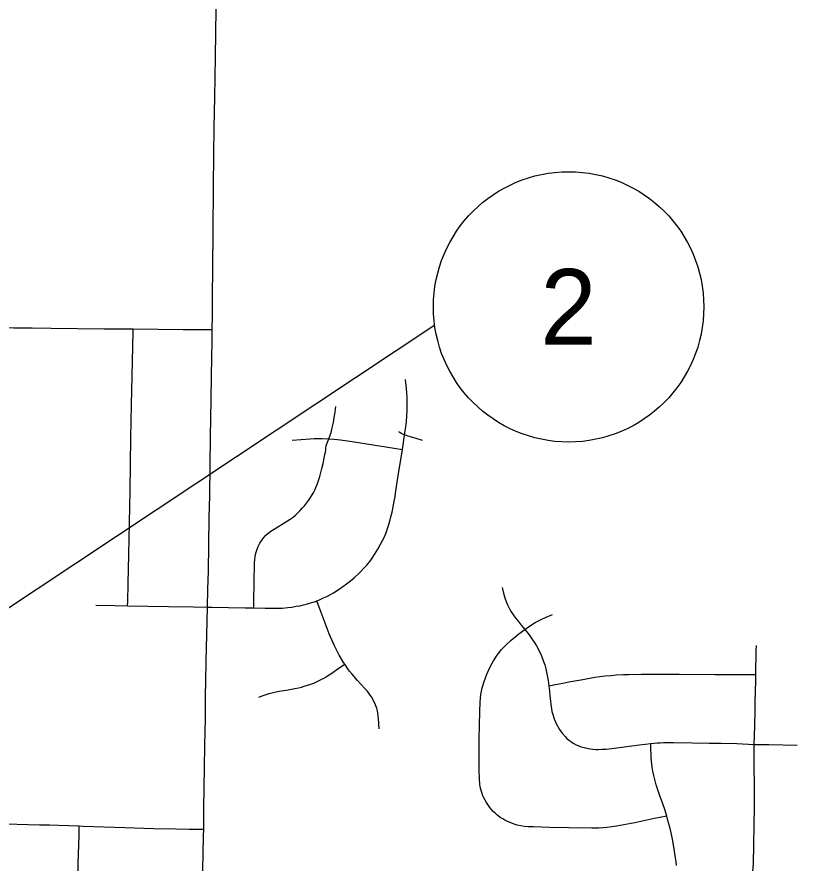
# Model space of a CAD drawing. Extents: x 1341221 to 1914484, y 79347 to 658398.
# Drawn here: x 1392720 to 1399302, y 615143 to 622283 of the extents above; entities that cross this region are included whole.
import ezdxf

# ---------------------------------------------------------------- set-up
doc = ezdxf.new("R2010")
doc.units = 0
for name, color, linetype in [('GM_X_County', 7, 'Continuous'), ('GM_X_State_Shield', 7, 'Continuous'), ('GM_X_US_Shield', 7, 'Continuous')]:
    doc.layers.add(name, color=color, linetype=linetype)

msp = doc.modelspace()

# ---------------------------------------------------------------- linework, layer by layer
at = {"layer": 'GM_X_County'}
msp.add_line((1396244.3, 619680.8), (1389506.6, 615209.7), dxfattribs=at)
msp.add_circle((1397374.4, 619836), 1140.7, dxfattribs=at)
at = {"layer": 'GM_X_State_Shield'}
for points in [[(1393653.5, 617314.5), (1393654.4, 617348.7), (1393658.6, 617500.9), (1393663.6, 617743.5), (1393673.9, 618283.1), (1393681.5, 618729.9), (1393687.4, 619010.9), (1393689.9, 619129.4), (1393696.7, 619499.2), (1393699.3, 619624.5), (1393699.8, 619649.6)], [(1393386.6, 617319.9), (1393546.9, 617316.6), (1393653.5, 617314.5), (1393999.3, 617307.6), (1394206.7, 617304.2), (1394328.3, 617301.3), (1394363.2, 617300.8), (1394644.8, 617297), (1394719, 617295.4), (1394812.6, 617293.2), (1394912.3, 617292.8), (1394956.5, 617294.9), (1395003.9, 617299.1), (1395039.4, 617303.4), (1395076.6, 617309.3), (1395105.4, 617314.4), (1395136.8, 617321.1), (1395172.3, 617329.6), (1395208.7, 617340.6), (1395237.5, 617350.7), (1395249, 617355.3), (1395272.1, 617364.3), (1395305.1, 617379.5), (1395333.1, 617393.1), (1395358.5, 617406.6), (1395389.8, 617424.4), (1395437.2, 617453.2), (1395469.4, 617475.2), (1395501.5, 617498.9), (1395532.8, 617523.4), (1395564.1, 617549.6), (1395607.3, 617590.3), (1395658.9, 617643.6), (1395670.9, 617657.4), (1395680.9, 617669), (1395698.7, 617691), (1395715.6, 617714.7), (1395736, 617746.9), (1395763.8, 617791.7), (1395785.5, 617827.5), (1395802, 617858.6), (1395814.7, 617884.4), (1395825.6, 617908.5), (1395837, 617937.4), (1395846.8, 617966.1), (1395855.1, 617992), (1395865.4, 618028.7), (1395874.8, 618063.4), (1395884.5, 618103.2), (1395894.2, 618148), (1395903.5, 618197.2), (1395910.3, 618232.3), (1395914.5, 618264.8), (1395934, 618394.3), (1395971.4, 618632.3), (1395993.3, 618774.3), (1396000, 618822.6), (1396005.1, 618868.2), (1396008.9, 618917.9), (1396011.9, 618960.5), (1396012.6, 619000.9), (1396012.7, 619040.1), (1396011.4, 619077.5), (1396009.3, 619106.1), (1396005.2, 619154), (1396000.9, 619194.1), (1395997.4, 619223.9)], [(1394719, 617295.4), (1394719.3, 617322.4), (1394721.9, 617546.7), (1394723.5, 617642.3), (1394724.4, 617675.7), (1394726.9, 617704.9), (1394729.5, 617726.1), (1394733.7, 617747.3), (1394738.8, 617766.7), (1394743.9, 617783.7), (1394755.7, 617814.1), (1394769.3, 617841.2), (1394781.9, 617861.5), (1394794.6, 617880.1), (1394805.6, 617893.7), (1394819.2, 617908.9), (1394832.7, 617921.6), (1394850.5, 617936), (1394870.8, 617949.5), (1394898.8, 617966.4), (1394980.8, 618015.6), (1395025.7, 618046), (1395050.3, 618062.9), (1395071.4, 618079.9), (1395090.9, 618098.5), (1395109.5, 618117.9), (1395128.9, 618139.1), (1395145.9, 618158.6), (1395162, 618178.9), (1395179.7, 618202.6), (1395195.8, 618226.3), (1395210.2, 618250), (1395220.4, 618267.8), (1395232.2, 618290.6), (1395242.4, 618312.6), (1395252.5, 618337.2), (1395265.2, 618371.9), (1395275.4, 618404), (1395284.7, 618437.9), (1395293.1, 618470.9), (1395303.3, 618514.9), (1395312.6, 618559.8), (1395318.5, 618590.2), (1395321.9, 618610.1), (1395324.5, 618627.4), (1395327, 618646.1), (1395329.5, 618664.7), (1395332.9, 618679.1), (1395350.6, 618722.3), (1395363.4, 618753.5), (1395370.1, 618775.5), (1395377.8, 618805.2), (1395389.7, 618861.1), (1395397.3, 618903.4), (1395402.3, 618930.4), (1395405.7, 618951.6), (1395408.3, 618971.9), (1395409.9, 618994)], [(1395938, 618785.5), (1395951.1, 618777.5), (1395962.6, 618771.3), (1395973.6, 618766), (1395992, 618757.7), (1396004.4, 618752.8), (1396016.6, 618748.5), (1396038.2, 618741.8), (1396086.2, 618727.3), (1396138.2, 618711.9)], [(1395042.2, 618712.3), (1395192.9, 618723.3), (1395228.4, 618725.1), (1395291.9, 618724.2), (1395350.6, 618722.3), (1395392.6, 618720.8), (1395421.4, 618718.3), (1395449.3, 618714.9), (1395549.1, 618698.8), (1395903.8, 618643), (1395971.4, 618632.3)], [(1396813.6, 617467.9), (1396816.8, 617455.5), (1396825.3, 617419), (1396836.8, 617380.9), (1396847.3, 617350.9), (1396859.8, 617321.8), (1396879.7, 617281.4), (1396890.9, 617261.7), (1396902.8, 617243.2), (1396921.3, 617217.2), (1396948.6, 617183.5), (1396975.1, 617151.4), (1397005.8, 617114.8), (1397040.4, 617067.9), (1397064.8, 617035.1), (1397088.3, 616999), (1397102.9, 616976), (1397120.5, 616943.8), (1397142.6, 616897.6), (1397152, 616874.3), (1397163.3, 616844), (1397173.1, 616814.7), (1397182, 616782.8), (1397194.4, 616726.6), (1397201.5, 616684.5), (1397206.8, 616639.5), (1397212.1, 616594.1), (1397216.7, 616554.7), (1397221.8, 616510.9), (1397225.1, 616479.4), (1397229.5, 616447.4), (1397233.6, 616421.8), (1397239.8, 616397.4), (1397251.3, 616360.8), (1397266.8, 616325.8), (1397298.3, 616270), (1397320.1, 616238.4), (1397345.1, 616209.5), (1397359.9, 616195.3), (1397373.3, 616183.4), (1397389.5, 616170.3), (1397404.2, 616160.6), (1397419.6, 616151.7), (1397437.7, 616141.9), (1397455.1, 616133.7), (1397473.1, 616127.2), (1397495.6, 616120.3), (1397516.1, 616114.6), (1397538.2, 616109.8), (1397560, 616106.2), (1397579.8, 616103.8), (1397604.6, 616102.3), (1397627.4, 616101.8), (1397655.8, 616102.6), (1397691.6, 616104.8), (1397738.6, 616109.7), (1397842.9, 616124), (1397971.2, 616141.1), (1398068.6, 616151.6), (1398097.4, 616154.9), (1398121.5, 616157.4), (1398146.1, 616158.7), (1398175.6, 616159.9), (1398212.8, 616159.2), (1398260.3, 616159.6), (1398419.7, 616156.5), (1398561.5, 616155), (1398661.7, 616153.2), (1398794, 616150.9), (1398940.4, 616142), (1399062.8, 616142.2), (1399301.9, 616139)], [(1395774.6, 616275.4), (1395771.3, 616362.5), (1395768.7, 616385.4), (1395765.3, 616408.2), (1395761.1, 616428.5), (1395755.1, 616450.5), (1395748.4, 616469.1), (1395740.8, 616486.9), (1395723, 616524.2), (1395712.9, 616541.9), (1395701, 616560.6), (1395689.1, 616576.6), (1395674.7, 616595.2), (1395655.3, 616616.4), (1395623.1, 616648.6), (1395591.8, 616682.4), (1395547, 616736.6), (1395526.6, 616762), (1395510.6, 616782.3), (1395485.1, 616820.5), (1395475, 616835.7), (1395438.6, 616898.2), (1395419.1, 616935.5), (1395398, 616977), (1395375.1, 617027.8), (1395354.8, 617076), (1395260.9, 617324), (1395249, 617355.3)], [(1398202.4, 615539.8), (1398083.6, 615514.9), (1397933.3, 615483.5), (1397778.7, 615453.8), (1397738.6, 615447.2), (1397696, 615442.8), (1397665.9, 615440.7), (1397628.4, 615438.7), (1397570.2, 615437.7), (1397373.3, 615439.1), (1397214.4, 615443.8), (1397078.7, 615447.8), (1397032, 615449.7), (1397003, 615451.8), (1396971.4, 615455.8), (1396940.4, 615462.8), (1396914.3, 615470.8), (1396882, 615483.9), (1396857.6, 615494.8), (1396835.6, 615505.7), (1396818.1, 615514.9), (1396797.3, 615528.7), (1396780.5, 615540.5), (1396766.5, 615551.7), (1396753.4, 615563.5), (1396738.7, 615578.1), (1396710.1, 615612.5), (1396681.1, 615654.7), (1396670.3, 615673.3), (1396659.5, 615693.9), (1396650.7, 615710.8), (1396644.3, 615729.2), (1396638.2, 615746.9), (1396633.2, 615765.8), (1396628.2, 615787.5), (1396625.2, 615809.9), (1396621.8, 615854.6), (1396620.5, 615927.3), (1396620.5, 615991.7), (1396620.8, 616193.7), (1396623.9, 616417.6), (1396627.3, 616500.7), (1396634.9, 616564.1), (1396645.8, 616620.7), (1396661.5, 616676), (1396683.5, 616736.1), (1396710.2, 616794.3), (1396740.9, 616850.4), (1396772.5, 616898.5), (1396808.2, 616943.6), (1396847.5, 616985.7), (1396889.8, 617024.7), (1396954.3, 617077.3), (1397005.8, 617114.8), (1397037.1, 617137.5), (1397091, 617172), (1397136.1, 617196), (1397185.7, 617218.2), (1397239.1, 617240.7)], [(1398296, 614779), (1398585.6, 614773.8), (1398641.8, 614779.5), (1398690.4, 614791), (1398737, 614808.8), (1398780.4, 614833.1), (1398814.7, 614859.8), (1398849.2, 614895.7), (1398878.6, 614936.1), (1398902.5, 614980), (1398917.9, 615020.6), (1398928.8, 615069.2), (1398934.5, 615138.3), (1398941.6, 615618.4), (1398940.4, 616142), (1398944.6, 616297), (1398945.4, 616316.5), (1398947.6, 616412.6), (1398949.6, 616504.1), (1398953.5, 616679.2), (1398954.5, 616734.6), (1398958.1, 616940.4), (1398959.8, 616978.6)], [(1394761.7, 616541.9), (1394797, 616556), (1394822.6, 616564.8), (1394847.1, 616572.4), (1394882.7, 616582.6), (1394906.4, 616588.5), (1394950.4, 616596.1), (1394993.6, 616602.8), (1395063.8, 616614.7), (1395096, 616621.5), (1395120.5, 616627.4), (1395143.4, 616634.2), (1395172.1, 616643.5), (1395199.3, 616652.8), (1395224.7, 616662.1), (1395247.5, 616672.3), (1395279.7, 616688.4), (1395314.3, 616707), (1395340.6, 616722.2), (1395368.5, 616739.9), (1395439.6, 616789.1), (1395485.1, 616820.5)], [(1397206.8, 616639.5), (1397264, 616650.3), (1397325, 616661.9), (1397375.6, 616671.5), (1397495.4, 616692.8), (1397596.3, 616710.8), (1397679, 616721.6), (1397732.7, 616726.6), (1397774.5, 616729.9), (1397837.9, 616733.1), (1397883.3, 616734.1), (1397989.2, 616735.7), (1398305.9, 616735.5), (1398606.6, 616734.8), (1398895.1, 616734.1), (1398954.5, 616734.6)], [(1398283.9, 615122.9), (1398280.9, 615153), (1398276.9, 615188), (1398271.4, 615222.6), (1398265.4, 615259.7), (1398259.4, 615295.3), (1398249.6, 615344.8), (1398238.8, 615397), (1398227.3, 615445.3), (1398212.8, 615500.7), (1398202.4, 615539.8), (1398187.7, 615587.4), (1398166.2, 615652), (1398153, 615688.2), (1398141.2, 615719.9), (1398124.6, 615769.3), (1398113.6, 615803.9), (1398105.1, 615836.3), (1398098.5, 615859.5), (1398093, 615882.5), (1398085.5, 615918.7), (1398080, 615950.7), (1398076.5, 615976.3), (1398073.5, 616003.8), (1398071, 616034.9), (1398069.5, 616063.5), (1398068.5, 616095), (1398069.2, 616126.6), (1398068.6, 616151.6)], [(1392625.9, 615474.3), (1392813.8, 615469.2), (1392908.6, 615466.7), (1392994.5, 615464.1), (1393070.3, 615461.6), (1393245.2, 615455.9), (1393279.3, 615454.9), (1393629.7, 615443), (1393871.7, 615435.4), (1394060.5, 615431.3), (1394173.9, 615428.6), (1394253.4, 615429.5), (1394295.8, 615429.9)], [(1393225.8, 614486.7), (1393227.5, 614553.5), (1393233.4, 614794), (1393237.6, 615138.1), (1393243.4, 615373.8), (1393244.4, 615419.3), (1393245.2, 615455.9)]]:
    msp.add_lwpolyline(points, dxfattribs=at)
at = {"layer": 'GM_X_US_Shield'}
for points in [[(1394294.3, 615368.5), (1394295.8, 615429.9), (1394296.4, 615457.4), (1394297.8, 615604.8), (1394302.2, 615949.5), (1394304.6, 616135.8), (1394307.6, 616253.5), (1394310.3, 616359.5), (1394311.8, 616551.3), (1394313.8, 616679.1), (1394317.3, 616845.2), (1394320.9, 617069.2), (1394328.3, 617301.3), (1394330.7, 617452.8), (1394334.9, 617606.3), (1394342.6, 618054.1), (1394346.3, 618245.9), (1394353.9, 618738.5), (1394358.4, 619052), (1394360.3, 619256.7), (1394366.1, 619550.7), (1394367.1, 619646.3), (1394368.4, 619761.7), (1394370.6, 619921.6), (1394372.6, 620164.7), (1394374.7, 620471.8), (1394378, 620849.2), (1394381.3, 621118), (1394384.1, 621348.3), (1394388.3, 621604.2), (1394393.9, 621943.3), (1394404.7, 622557.2)], [(1391796.9, 619670.5), (1392350.5, 619663.1), (1392693.9, 619660.5), (1392849, 619658.9), (1393007.5, 619656.2), (1393229.9, 619653), (1393455.4, 619651.6), (1393699.8, 619649.6), (1394122, 619646.3), (1394328.4, 619646.3), (1394367.1, 619646.3)], [(1394259.5, 614453.3), (1394272.3, 614746.4), (1394280.7, 614936.6), (1394287.2, 615081.9), (1394294.3, 615368.5)]]:
    msp.add_lwpolyline(points, dxfattribs=at)

# ---------------------------------------------------------------- texts
at = {"layer": 'GM_X_County'}
msp.add_text('2', height=638.8, dxfattribs=at).set_placement((1397136, 619516.6))

doc.saveas('drawing.dxf')
